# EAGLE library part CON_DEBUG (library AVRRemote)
PIN HEADER
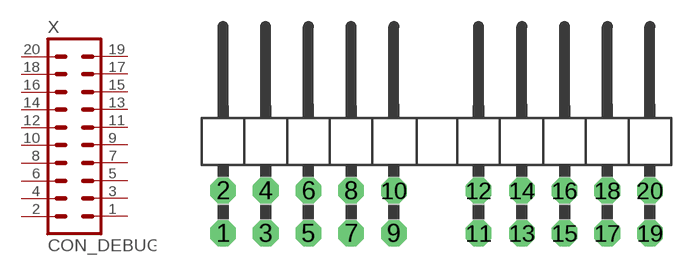
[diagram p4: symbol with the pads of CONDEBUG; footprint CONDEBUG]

Designator prefix X

## CON_DEBUG  [CONDEBUG]
1  1  pas
2  2  pas
3  3  pas
4  4  pas
5  5  pas
6  6  pas
7  7  pas
8  8  pas
9  9  pas
10  10  pas
11  11  pas
12  12  pas
13  13  pas
14  14  pas
15  15  pas
16  16  pas
17  17  pas
18  18  pas
19  19  pas
20  20  pas

## Footprint CONDEBUG (pad centres in mm)
PIN HEADER
drill 1.016 octagon: 1 -13.97,-1.27; 2 -13.97,1.27; 3 -11.43,-1.27; 4 -11.43,1.27; 5 -8.89,-1.27; 6 -8.89,1.27; 7 -6.35,-1.27; 8 -6.35,1.27; 9 -3.81,-1.27; 10 -3.81,1.27; 11 1.23,-1.27; 12 1.23,1.27; 13 3.81,-1.27; 14 3.81,1.27; 15 6.35,-1.27; 16 6.35,1.27; 17 8.89,-1.27; 18 8.89,1.27; 19 11.43,-1.27; 20 11.43,1.27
